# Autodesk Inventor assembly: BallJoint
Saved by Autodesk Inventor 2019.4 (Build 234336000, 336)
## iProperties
Created: 2020-04
Part Number: BallJoint
Document SubType Name: Assembly
Designer: Administrator
Title: BallJoint v14
Author: Administrator
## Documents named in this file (3)
- c:\worker\convert-fusion-r03\tmp\job-1\48\output\files\ccae6ef3-9f0e-42ff-b199-3a2c6474057a\BallJoint v14_1.iam
- c:\worker\convert-fusion-r03\tmp\job-1\48\output\files\ccae6ef3-9f0e-42ff-b199-3a2c6474057a\Component1_1.ipt
- c:\worker\convert-fusion-r03\tmp\job-1\48\output\files\ccae6ef3-9f0e-42ff-b199-3a2c6474057a\Component2_1.ipt
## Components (2 placed, 2 different names)
1. Component1:1
2. Component2:1
